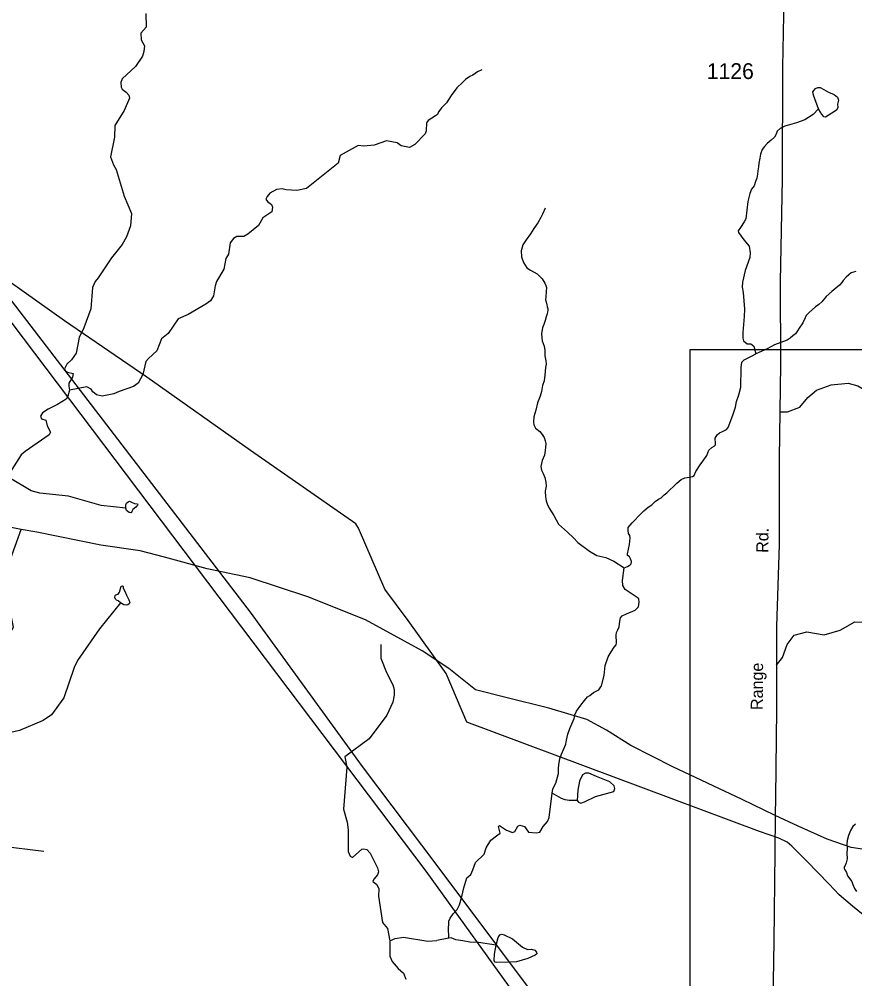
# Model space of a CAD drawing. Extents: x 2056842 to 2160602, y 826753 to 1016856.
# Drawn here: x 2070531 to 2077140, y 894365 to 901949 of the extents above; entities that cross this region are included whole.
import ezdxf

# ---------------------------------------------------------------- set-up
doc = ezdxf.new("R2010")
doc.units = 0
for name, color, linetype in [('Exist Hydrographic Creek Single Shore', 7, 'Continuous'), ('Exist Hydrographic Misc Water Feature', 7, 'Continuous'), ('Exist Road Non-System Type 51', 7, 'Continuous'), ('Exist Road Secondary Type 51 Attributed', 7, 'Continuous'), ('Exist Road Secondary Type 51 Label', 7, 'Continuous'), ('Exist Road Secondary Type 51 Number Label', 7, 'Continuous'), ('Exist Utilities Electrical Transmission Line', 7, 'Continuous'), ('Map Preparation Inset Cut Line', 7, 'Continuous')]:
    doc.layers.add(name, color=color, linetype=linetype)

msp = doc.modelspace()

# ---------------------------------------------------------------- linework, layer by layer
at = {"layer": 'Exist Hydrographic Creek Single Shore'}
for points in [[(2071531.1, 901992.9), (2071535, 901886.8), (2071493.6, 901837.2), (2071495.6, 901784.9), (2071521.7, 901737.1), (2071517.6, 901693.1), (2071505.7, 901657.2), (2071449.9, 901575.2)], [(2071449.9, 901575.2), (2071346.1, 901476.8), (2071334, 901448.6), (2071336.3, 901412.6), (2071344.3, 901396.8), (2071376.3, 901372.9), (2071398.2, 901348.9), (2071404.4, 901324.8), (2071360.5, 901226.8), (2071288.5, 901108.6), (2071284.6, 901016.7), (2071253.2, 900860.8), (2071277.2, 900798.6), (2071297.3, 900760.7), (2071359.7, 900550.8), (2071419.9, 900413), (2071411.9, 900316.7), (2071380.4, 900229.1), (2071344.5, 900166.8), (2071260.4, 900062.6), (2071155.2, 899904.5), (2071131, 899876.5), (2071110.9, 899828.4), (2071097.4, 899660.5), (2071041.6, 899508.2), (2071003.9, 899432.4), (2070981.8, 899310.4), (2070944.2, 899255.9), (2070906.3, 899222), (2070888.5, 899186.1), (2070896.4, 899169.9), (2070912.6, 899160.2), (2070956.5, 899148.2), (2070952.2, 899120.1), (2070924.7, 899072.3), (2070922.5, 899048.3), (2070928.6, 899016.1)], [(2076851.5, 901240.6), (2076810.3, 901195.6), (2076743, 901153.2), (2076678.1, 901130.7), (2076586, 901103.3), (2076548.3, 901085.2), (2076524.1, 901062.8), (2076518, 901039), (2076504.2, 901015.2), (2076478.6, 900993.1), (2076446.6, 900966.7), (2076424.2, 900942.9), (2076406.6, 900918.8), (2076394.7, 900880.7), (2076389, 900850.4), (2076381, 900810.6), (2076378.9, 900782.5), (2076373.2, 900750.5), (2076369.3, 900724.8), (2076363.3, 900692.4), (2076353.3, 900664.7), (2076343.2, 900632.5), (2076321.5, 900604.5), (2076309.1, 900571.1), (2076292.9, 900507.4), (2076277.9, 900370.1), (2076265.5, 900347.7), (2076234.3, 900302.7), (2076218.1, 900275.3), (2076219.3, 900261.5), (2076263, 900205.4), (2076302.9, 900154.2), (2076312.9, 900101.8), (2076310.4, 900064.1), (2076271.7, 899961.7), (2076250.5, 899870.6), (2076248, 899831.9), (2076256.7, 899789.5), (2076266.6, 899656.5), (2076265.5, 899598.5), (2076254.2, 899473.7), (2076253, 899428.8), (2076259.2, 899407.6), (2076289.2, 899383.8), (2076317.8, 899382.1), (2076341.5, 899363.4), (2076356.5, 899303.5)], [(2073256.6, 900944.4), (2073212.9, 900950.3), (2073069.2, 900871.8), (2073053.2, 900809.7), (2072801.8, 900611.6), (2072725.5, 900595.2), (2072641.2, 900599.1), (2072609.5, 900607.1), (2072565.4, 900602.9), (2072513.7, 900573), (2072491.5, 900547.1), (2072481.7, 900527), (2072493.8, 900507), (2072525.8, 900483), (2072534, 900462.7), (2072529.7, 900426.9), (2072457.9, 900378.9), (2072424.1, 900318.7), (2072340.2, 900248.7), (2072308.2, 900232.4), (2072252, 900232.4), (2072224.4, 900216.3), (2072200.6, 900180.6), (2072186.4, 900092.6), (2072164.5, 900056.1), (2072148.7, 899974.1), (2072090.9, 899876.2), (2072081, 899840.4), (2072067.1, 899762.1), (2072043.5, 899722.3), (2072007.2, 899696.2), (2071867.4, 899615.9), (2071787.6, 899581.7), (2071708, 899465.6), (2071656, 899423.5), (2071619.9, 899327.6), (2071552.2, 899267.3), (2071532.1, 899243.5), (2071508.1, 899141.2), (2071472.2, 899071.2), (2071434.3, 899044.9), (2071320.5, 899007), (2071280.5, 898988.6), (2071186.6, 898968.8), (2071142.7, 898980.3), (2071112.8, 899004.4), (2071100.3, 899024.5), (2071066.4, 899042.2), (2070928.6, 899016.1)], [(2074690.5, 900455.5), (2074672.5, 900413.1), (2074656.5, 900381), (2074632.9, 900339.2), (2074600.5, 900295), (2074574.9, 900253.1), (2074540.8, 900205), (2074515, 900164.7), (2074501.5, 900118.9), (2074503.3, 900070.8), (2074519.7, 900024.9), (2074545.4, 899984.8), (2074574.1, 899965.1), (2074628.2, 899935.4), (2074665.9, 899897.1), (2074687.9, 899863.4), (2074696.1, 899843.5), (2074702.4, 899827.5), (2074698.3, 899795.3), (2074694.6, 899755.2), (2074694.4, 899731.3), (2074700.4, 899703.6), (2074704.9, 899691.5), (2074706.7, 899675.4), (2074710.8, 899663.5), (2074712.7, 899647.4), (2074708.6, 899635.5), (2074706.9, 899619.5), (2074698.9, 899595.5), (2074689.3, 899567.4), (2074679.2, 899535.2), (2074669.4, 899509.5), (2074661.2, 899465.3), (2074665.3, 899429.3), (2074667.8, 899405.4), (2074681.7, 899363.6), (2074687.7, 899331.4), (2074687.7, 899287.6), (2074695.9, 899247.4), (2074698.3, 899223.5), (2074694.4, 899195.2), (2074688.7, 899135.2), (2074682.7, 899091.6), (2074668.6, 899053.4), (2074662.8, 899005.2), (2074650.7, 898969.4), (2074631.1, 898917.2), (2074617.1, 898859.1), (2074601.3, 898807.3), (2074599.5, 898763.3), (2074601.7, 898743.1), (2074605.6, 898731.1), (2074613.6, 898715.3), (2074647.5, 898689.5), (2074665.7, 898665.6), (2074681.9, 898643.2), (2074691.8, 898615.7), (2074696.1, 898595.6), (2074694.4, 898567.4), (2074690.1, 898539.4), (2074684.2, 898503.3), (2074666.5, 898461.3), (2074656.3, 898413.4), (2074660.6, 898385.5), (2074674.5, 898359.4), (2074688.9, 898325.6), (2074696.9, 898289.5), (2074698.9, 898257.6), (2074689.3, 898217.6), (2074693.4, 898173.5), (2074699.5, 898141.5), (2074706.9, 898117.7), (2074721.9, 898084), (2074758.1, 898026.6), (2074795.5, 897956.7), (2074868.3, 897894.3), (2074914.4, 897850.3), (2074948.5, 897812.2), (2075040.6, 897744.8), (2075098.1, 897710.8), (2075170.8, 897695), (2075232.9, 897665.2), (2075314.9, 897613.4)], [(2077147.5, 899955), (2077111.8, 899945), (2077093.3, 899928.7), (2077071.8, 899908.9), (2077047.8, 899882.9), (2077035.7, 899868.9), (2077018.1, 899846.8), (2076988.1, 899822.6), (2076958.2, 899796.6), (2076911.9, 899758.2), (2076878.6, 899716.2), (2076854.6, 899694.3), (2076828.2, 899674.3), (2076778.8, 899631.9), (2076754.8, 899608), (2076746.8, 899588.1), (2076729, 899549.8), (2076699, 899507.6), (2076685.1, 899485.8), (2076669.3, 899461.5), (2076649.2, 899445.4), (2076627.4, 899427.6), (2076605.3, 899411.5), (2076505, 899375.9), (2076447.6, 899344.7), (2076356.5, 899303.5)], [(2075314.9, 897613.3), (2075343, 897623.5), (2075354.9, 897631.5), (2075362.9, 897635.6), (2075370.7, 897645.6), (2075372.6, 897661.6), (2075366.5, 897683.4), (2075358.6, 897699.3), (2075346.7, 897707.4), (2075342.5, 897711.5), (2075342.4, 897723.3), (2075357.1, 897797.2), (2075362.1, 897849.6), (2075360.8, 897869.6), (2075349.6, 897884.6), (2075345.9, 897907.1), (2075348.3, 897930.8), (2075378.3, 897968.2), (2075449.4, 898041.6), (2075471.5, 898063.8), (2075505.2, 898092), (2075535.1, 898110.1), (2075559.3, 898136.2), (2075587.3, 898156.3), (2075609.1, 898166.3), (2075631, 898190.1), (2075653, 898206.4), (2075677, 898228.6), (2075706.8, 898256.5), (2075732.6, 898282.5), (2075767, 898310), (2075794.4, 898324.9), (2075833.1, 898328.7), (2075856.8, 898333.7), (2075869.3, 898343.7), (2075883, 898373.6), (2075915.4, 898426), (2075945.4, 898466), (2075970.3, 898500.9), (2075985.3, 898543.4), (2076009, 898564.6), (2076026.4, 898574.6), (2076036.4, 898584.5), (2076037.7, 898595.5), (2076034.7, 898638.5), (2076049.6, 898663.4), (2076068.4, 898678.4), (2076092.1, 898690.9), (2076124.5, 898707.1), (2076138.2, 898722.1), (2076174.4, 898819.4), (2076195.6, 898882.1), (2076203.1, 898928.3), (2076223, 898980.7), (2076239.3, 899040.6), (2076240.5, 899194.1), (2076246.7, 899239.1), (2076265.5, 899256.5), (2076321.6, 899284.7), (2076356.5, 899303.5)], [(2070928.6, 899016.1), (2070914.7, 898968.2), (2070902.8, 898946.1), (2070834.7, 898904.1), (2070761.1, 898867.7), (2070715, 898837.9), (2070699, 898811.9), (2070706.8, 898789.6), (2070741, 898780), (2070751.1, 898735.8), (2070779.2, 898686.1), (2070767.1, 898664), (2070577.6, 898531.6), (2070545.6, 898505.6), (2070473.8, 898391.1), (2070449.8, 898325.4)], [(2074746.6, 895831.1), (2074752.4, 895865.8), (2074774.3, 895911.6), (2074795.9, 895987.9), (2074796, 896024.9), (2074798.5, 896059.8), (2074806, 896102.3), (2074819.7, 896140.9), (2074838.4, 896182.1), (2074854.6, 896218.3), (2074859.1, 896250.1), (2074869, 896298.2), (2074885.8, 896341.9), (2074904.5, 896384.8), (2074919.5, 896422.8), (2074925.7, 896451.5), (2074938.2, 896480.2), (2074973.1, 896527.6), (2075000.6, 896563.8), (2075026, 896592.5), (2075044, 896604.6), (2075072.4, 896628.7), (2075093.6, 896637.5), (2075116.1, 896648.7), (2075136, 896679.9), (2075156, 896761), (2075165.3, 896841), (2075189.1, 896909.1), (2075212.1, 896949.2), (2075235.8, 896986.7), (2075250.8, 897004.2), (2075254.5, 897020.4), (2075252, 897080.3), (2075254.5, 897102.8), (2075264.5, 897124), (2075277, 897146.4), (2075282, 897192.6), (2075285.7, 897218.8), (2075300.7, 897233.8), (2075334.4, 897248.8), (2075403, 897278.7), (2075427.9, 897305), (2075434.2, 897341.2), (2075430.4, 897366.6), (2075419.2, 897379.1), (2075324.4, 897441.5), (2075305.7, 897474), (2075301.9, 897512.6), (2075314.9, 897613.3)], [(2073390.5, 897006.7), (2073390.6, 896898.7), (2073434.9, 896784.7), (2073485.1, 896686.9), (2073497.1, 896651), (2073497.2, 896607), (2073485.3, 896550.9), (2073439.5, 896448.8), (2073299.9, 896262.6), (2073106.3, 896118.2), (2073122.4, 896038.3), (2073096.9, 895706.3), (2073125.2, 895602.3), (2073133.2, 895542.4), (2073133.6, 895370.3), (2073149.7, 895334.4), (2073165.7, 895324.5), (2073241.4, 895390.5), (2073257.5, 895392.6), (2073279.6, 895386.5), (2073305.6, 895358.6), (2073363.8, 895242.8), (2073371.7, 895210.8), (2073363.8, 895186.8), (2073335.9, 895152.7), (2073328, 895134.7), (2073360.1, 895110.8), (2073376.1, 895074.9), (2073372.2, 895018.8), (2073404.6, 894808.9), (2073444.7, 894763), (2073460.9, 894665.1)], [(2073928, 894687.1), (2073925.8, 894771.2), (2073927.7, 894795.1), (2073929.8, 894819.3), (2073939.5, 894843.1), (2073963.5, 894879.3), (2073993.4, 894913.5), (2074013.2, 894949.5), (2074030.8, 895014.6), (2074048.3, 895083.3), (2074070.7, 895161.9), (2074103.2, 895188.1), (2074118.1, 895225.6), (2074140.6, 895283), (2074208.7, 895349.1), (2074223.7, 895400.3), (2074259.8, 895461.5), (2074304.8, 895493.9), (2074333.4, 895516.4), (2074321, 895568.8), (2074328.5, 895577.5), (2074384.6, 895540.1), (2074433.2, 895521.4), (2074452, 895528.9), (2074475.7, 895571.3), (2074490.6, 895578.8), (2074526.8, 895568.8), (2074559.2, 895523.9), (2074620.4, 895517.6), (2074647.8, 895522.6), (2074673.7, 895568.1), (2074708.7, 895608), (2074722.4, 895639.2), (2074746.6, 895831.1)], [(2077145.4, 895587.3), (2077123.5, 895567.4), (2077105.2, 895537.4), (2077089.6, 895497.1), (2077079.6, 895457.2), (2077075.7, 895429), (2077077.7, 895393), (2077076.1, 895357.2), (2077077.9, 895313.1), (2077072.2, 895281), (2077062.2, 895261.1), (2077054.2, 895249.3), (2077054.4, 895237.1), (2077060.3, 895225.2), (2077074.5, 895205.2), (2077082.5, 895179.3), (2077116.3, 895135.2), (2077122.7, 895111.5), (2077136.8, 895079.3), (2077152.8, 895055.3)], [(2073460.9, 894665.1), (2073504.9, 894683.2), (2073568.9, 894693.3), (2073762.9, 894663.7), (2073832.5, 894666.7)], [(2073460.9, 894665.1), (2073461, 894545.1), (2073481.1, 894501), (2073529.3, 894445.2), (2073571.4, 894409.2), (2073589.5, 894363.2)]]:
    msp.add_lwpolyline(points, dxfattribs=at)
at = {"layer": 'Exist Hydrographic Misc Water Feature'}
for points in [[(2074190.8, 901547.8), (2074154.9, 901533.7), (2074119.3, 901505.4), (2074095.1, 901495.4), (2074061.2, 901471.3), (2074037.2, 901449.4), (2073991.1, 901407.2), (2073947.6, 901344.9), (2073911.5, 901287), (2073885.9, 901262.9), (2073870.1, 901246.7), (2073857.6, 901230.7), (2073848, 901216.7), (2073837.9, 901194.7), (2073824, 901184.6)], [(2076851.5, 901240.6), (2076812.8, 901347.9), (2076806.6, 901374.1), (2076827.8, 901401.6), (2076847.7, 901409.1), (2076866.5, 901409.1), (2076895.2, 901392.8), (2076931.3, 901371.6), (2076975, 901354.2), (2077002.4, 901332.9), (2077011.2, 901308), (2077003.7, 901278), (2077004.9, 901251.8), (2076996.2, 901233.1), (2076978.7, 901219.4), (2076906.4, 901173.2), (2076893.9, 901176.9), (2076870.2, 901208.1), (2076851.5, 901240.6)], [(2073824, 901184.6), (2073764.5, 901148.6), (2073752.6, 901128.4), (2073750.6, 901065.1), (2073740.5, 901043), (2073660.8, 900957), (2073616.7, 900934.9), (2073552.9, 900947), (2073519.1, 900970.8), (2073437, 900988.5), (2073337, 900952.5), (2073256.6, 900944.4)], [(2071374.7, 898083.6), (2071178.4, 898104.5), (2070921.9, 898180.3), (2070694.3, 898203.9), (2070625.8, 898221.5), (2070449.8, 898325.4)], [(2071374.7, 898083.6), (2071375.3, 898110.2), (2071379.8, 898122.8), (2071391.8, 898135.5), (2071404.4, 898138.7), (2071417.7, 898132.3), (2071442.4, 898121.6), (2071465.9, 898119), (2071469.6, 898114.6), (2071467.1, 898108.9), (2071453.2, 898093.1), (2071430.4, 898072.8), (2071422.2, 898057.6), (2071420.3, 898050), (2071413.9, 898047.5), (2071400, 898049.4), (2071379.1, 898064.6), (2071374.7, 898083.6)], [(2071333, 897334.9), (2071313.3, 897352.7), (2071300, 897357.7), (2071291.2, 897364.7), (2071287.4, 897378.6), (2071288.7, 897395.1), (2071294.3, 897400.2), (2071303.2, 897401.4), (2071312.7, 897405.9), (2071325.4, 897419.8), (2071336.1, 897466.7), (2071348.2, 897471.8), (2071350.7, 897469.9), (2071352, 897463.5), (2071353.2, 897450.8), (2071365.9, 897428.7), (2071380.4, 897397.6), (2071397.5, 897360.9), (2071405.1, 897338.1), (2071401.3, 897327.3), (2071389.9, 897319.7), (2071376, 897317.2), (2071358.3, 897319.7), (2071333, 897334.9)], [(2071333, 897334.9), (2071166.1, 897130.8), (2070992.6, 896880.4), (2070966.6, 896826.2), (2070882.9, 896586.1), (2070785.5, 896450), (2070721.1, 896406.2), (2070533.5, 896327.5), (2070407.6, 896299.5)], [(2074943.2, 895775.2), (2074953.2, 895760.3), (2074971.9, 895754), (2075001.8, 895762.8), (2075089.1, 895806.4), (2075233.8, 895846.4), (2075242.6, 895868.9), (2075235.1, 895890.1), (2075201.4, 895922.5), (2075095.4, 895965), (2075036.7, 895991.2), (2075010.5, 895991.2), (2074986.8, 895976.2), (2074963.1, 895927.5), (2074949.4, 895856.4), (2074943.2, 895775.2)], [(2074943.2, 895775.2), (2074879.6, 895774), (2074849.6, 895779), (2074819.7, 895790.2), (2074746.6, 895831.1)], [(2074302.8, 894630.5), (2074317.7, 894690.4), (2074332.7, 894711.6), (2074348.9, 894716.6), (2074367.6, 894712.8), (2074431.2, 894680.4), (2074511.1, 894614.2), (2074549.8, 894596.8), (2074582.2, 894600.5), (2074609.6, 894590.5), (2074623.3, 894576.8), (2074624.6, 894561.8), (2074610.9, 894553.1), (2074552.2, 894524.4), (2074463.7, 894498.2), (2074417.5, 894495.7), (2074309, 894493.2), (2074294, 894496.9), (2074286.5, 894506.9), (2074289, 894559.3), (2074302.8, 894630.5)], [(2073928, 894687.1), (2073832.5, 894666.7)], [(2074302.8, 894630.5), (2074162.1, 894652.3), (2074094.4, 894654), (2074038.3, 894665.8), (2073984.3, 894673.6), (2073948.2, 894687.6), (2073928.3, 894687.4)]]:
    msp.add_lwpolyline(points, dxfattribs=at)
at = {"layer": 'Exist Road Non-System Type 51'}
for points in [[(2076546.5, 898845), (2076608.1, 898845), (2076703.4, 898883.8), (2076768.9, 898958.3), (2076836, 899017.9), (2076953.6, 899059.7), (2077087.7, 899073.1), (2077163.7, 899052.2), (2077296.2, 898974.7), (2077368.5, 898896.4)], [(2070545.5, 897914.9), (2070386.1, 897946.2), (2070231.2, 898014.8), (2070040.6, 898092.3), (2069775.4, 898274.1), (2069540.1, 898429.1), (2069091.7, 898725.8), (2069008.3, 898776.5), (2068844.4, 898812.2), (2068543.5, 898862.9), (2068355.9, 898892.7), (2068230.7, 898880.8), (2068057.9, 898856.9), (2067846.4, 898791.4), (2067766, 898749.6), (2067597.7, 898670.6)], [(2069391.8, 896595), (2069555.7, 896699.3), (2070153, 896942.3), (2070445, 897076.5), (2070486.7, 897145), (2070465.8, 897249.4), (2070403.3, 897425.2), (2070415.2, 897550.5), (2070545.5, 897914.9)], [(2076509.9, 895655.9), (2076249.1, 895781.9), (2075700.9, 896041.2), (2075367.2, 896208.2), (2075175.1, 896328.9), (2075020.2, 896415.4), (2074719.3, 896504.8), (2074379.7, 896588.3), (2074138.4, 896647.9), (2073929.8, 896817.8), (2073716.8, 896956.5), (2073269.9, 897200.9), (2072814.1, 897382.8), (2072358.3, 897534.8), (2072017.2, 897604.9), (2071680.6, 897697.3), (2071486.9, 897748), (2071177.1, 897792.7), (2070670.6, 897894), (2070545.5, 897914.9)], [(2076519.6, 896842.7), (2076567.1, 896903.5), (2076605.8, 897007.9), (2076659.4, 897079.4), (2076760.7, 897106.3), (2076897.8, 897082.4), (2077022.9, 897121.2), (2077139.1, 897186.8), (2077380.4, 897180.8), (2077597.9, 897145), (2077699.2, 897124.2), (2077734.9, 897109.2), (2078038.8, 897004.9)], [(2069315.9, 895314.6), (2069715.1, 895398.1), (2070021.9, 895418.9), (2070379.4, 895416), (2070725, 895374.2)]]:
    msp.add_lwpolyline(points, dxfattribs=at)
at = {"layer": 'Exist Road Secondary Type 51 Attributed'}
for points in [[(2076581.2, 902257.5), (2076567.7, 901568.1), (2076565, 900684.6), (2076547.9, 899874.8), (2076552.4, 899219.6), (2076540.7, 898478.1), (2076541.6, 897797.7), (2076519.2, 897147.9), (2076520.1, 896494.5), (2076512, 895801.5), (2076509.9, 895655.9)], [(2080868, 895982.2), (2080810.5, 895985.8), (2080747.7, 895980.4), (2080452.2, 895923.7), (2080015.6, 895844.7), (2079421.9, 895734.1), (2078996.2, 895664), (2078469, 895591.2), (2078188.7, 895533.7), (2077881.5, 895460), (2077635.4, 895404.2), (2077422.6, 895372.8), (2077287.8, 895376.4), (2077110, 895403.3), (2076919.6, 895468), (2076691.4, 895570.5), (2076509.9, 895655.9)], [(2076509.9, 895655.9), (2076506.4, 895365.6), (2076498.3, 894660), (2076488.4, 894031.7), (2076488.4, 893675.8), (2076480.3, 893033.1), (2076474.1, 892194.5), (2076458.8, 891654.3), (2076458.8, 891354.1)]]:
    msp.add_lwpolyline(points, dxfattribs=at)
at = {"layer": 'Exist Utilities Electrical Transmission Line'}
for points in [[(2079289.6, 845905.8), (2079948.4, 849305.4), (2079483.2, 855866.2), (2080101, 858353.8), (2081583.8, 864201.8), (2082616, 868304.1), (2080660.7, 871519), (2079505, 873046.5), (2077150, 875999.6), (2076168.7, 877076.1), (2079417.8, 882691.3), (2077477.1, 888146.6), (2075950.7, 892161.6), (2073748.3, 895216.6), (2070106.7, 900031.7)], [(2070228.8, 900032.1), (2072358.2, 897262.8), (2073244.3, 896042.6), (2073834.2, 895260.3), (2077530.5, 890329.4), (2077620.9, 890191.7), (2078985.5, 888634.2), (2079057.9, 888552.5), (2080356.6, 887331.2), (2080736.5, 886973.8)], [(2077206.4, 894870), (2077120.2, 894937.8), (2077015.8, 895029.4), (2076937.6, 895113.2), (2076757, 895296.5), (2076640.7, 895412.1), (2076604.6, 895446.1), (2076538.4, 895475.9), (2076386.3, 895529.4), (2074070.8, 896393), (2073907.7, 896777), (2073607.9, 897197.8), (2073423.8, 897445), (2073214.8, 897926.2), (2073192.7, 897960.3), (2072359.8, 898538.8), (2071540.7, 899119.2), (2070888, 899565.9), (2070228.8, 900032.1)]]:
    msp.add_lwpolyline(points, dxfattribs=at)
at = {"layer": 'Map Preparation Inset Cut Line'}
msp.add_lwpolyline([(2075837.6, 899339.2), (2086885.8, 899339.2), (2086885.8, 887416.1), (2075837.6, 887416.1), (2075837.6, 899339.2)], dxfattribs=at)

# ---------------------------------------------------------------- texts
at = {"layer": 'Exist Road Secondary Type 51 Label'}
for s, rotation, p in [('Rd.', 89.25517, (2076454.8, 897730.8)), ('Range', 89.65513, (2076411.7, 896488.9))]:
    msp.add_text(s, height=95, rotation=rotation, dxfattribs=at).set_placement(p)
at = {"layer": 'Exist Road Secondary Type 51 Number Label'}
msp.add_text('1126', height=125, dxfattribs=at).set_placement((2075968.9, 901475.7))

doc.saveas('drawing.dxf')
